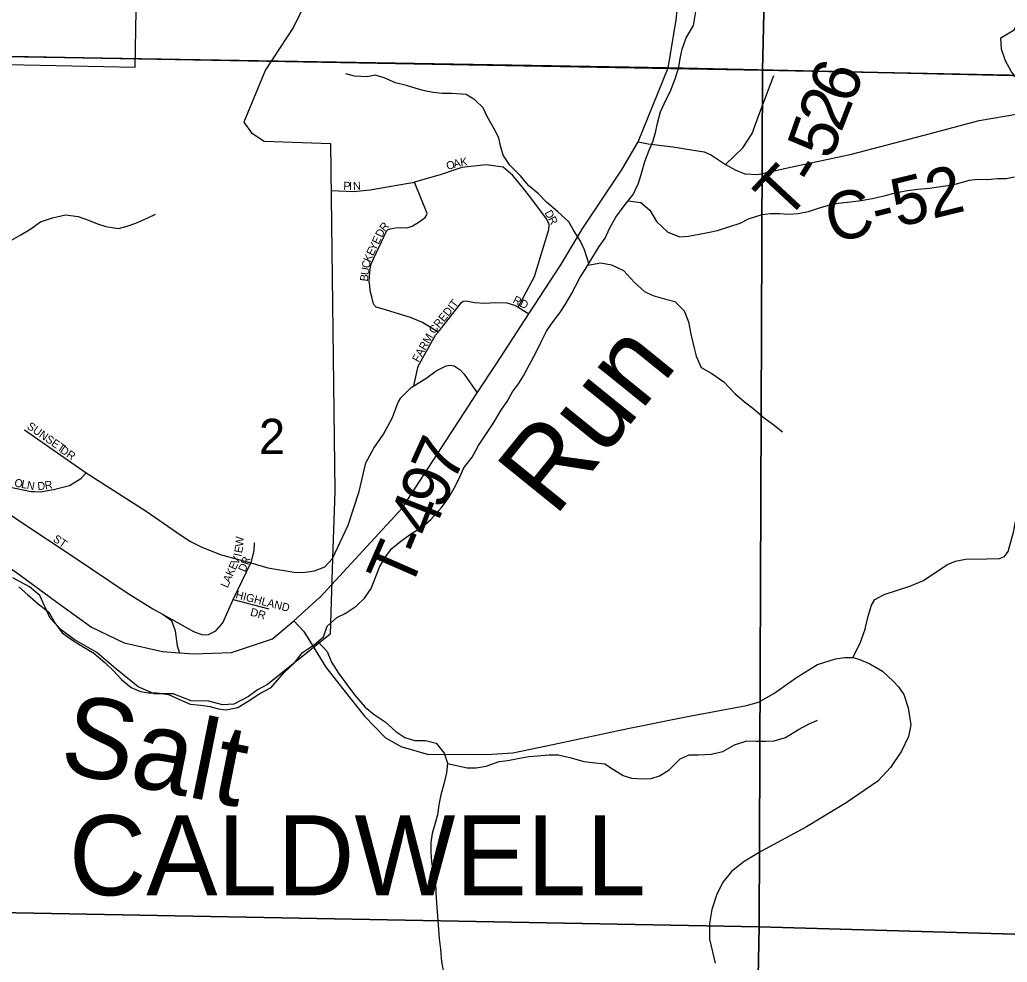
# Model space of a CAD drawing. Extents: x 2043100 to 2470832, y 443715 to 810583.
# Drawn here: x 2248144 to 2254313, y 633122 to 639011 of the extents above; entities that cross this region are included whole.
import ezdxf

# ---------------------------------------------------------------- set-up
doc = ezdxf.new("R2010")
doc.units = 0
for name, color, linetype in [('GM_X_City_Street', 7, 'Continuous'), ('GM_X_City_Street_Text', 7, 'Continuous'), ('GM_X_Corporation', 7, 'Continuous'), ('GM_X_Corporation_Text', 7, 'Continuous'), ('GM_X_County_Road', 7, 'Continuous'), ('GM_X_County_Road_Text', 7, 'Continuous'), ('GM_X_Minor_River', 7, 'Continuous'), ('GM_X_Minor_River_Text', 7, 'Continuous'), ('GM_X_Section', 7, 'Continuous'), ('GM_X_Section_Text', 7, 'Continuous'), ('GM_X_State_Route', 7, 'Continuous'), ('GM_X_Township', 7, 'Continuous'), ('GM_X_Township_Road', 7, 'Continuous'), ('GM_X_Township_Road_Text', 7, 'Continuous'), ('GM_X_Township_Subdivision', 7, 'Continuous'), ('GM_X_Township_Subdivision_Text', 7, 'Continuous')]:
    doc.layers.add(name, color=color, linetype=linetype)

msp = doc.modelspace()

# ---------------------------------------------------------------- linework, layer by layer
at = {"layer": 'GM_X_City_Street'}
for points in [[(2246916.4, 636617.1), (2246919.8, 636615.1), (2247083.8, 636528.3), (2247237.6, 636457.6), (2247393.3, 636382.9), (2247469.1, 636346.6), (2247533, 636314.3), (2247678.5, 636203.6), (2247905.2, 636042.7), (2248145.2, 635877.5), (2248484.3, 635651.9), (2248815.4, 635430.4), (2248975, 635329.7), (2249040.9, 635295.4), (2249092.7, 635257.2), (2249114.4, 635193), (2249128.1, 635098.9), (2249142.1, 635055.9)], [(2248173.5, 636448), (2248559.7, 636180.3), (2248933.5, 635940.5), (2249150.9, 635789.5), (2249210.7, 635751.2), (2249278.6, 635716.9), (2249396.4, 635670.4), (2249518.3, 635635.9), (2249587.9, 635616.6), (2249694.1, 635587.2), (2249858.6, 635559.7), (2249912.7, 635557), (2249986.4, 635566.8), (2250049.8, 635592.4), (2250098.3, 635644.2)], [(2248236.6, 636062.6), (2248237.1, 636062.6), (2248274, 636061.2), (2248356, 636074.9), (2248456.1, 636100.5), (2248526.3, 636144.3), (2248559.7, 636180.3)], [(2247905.2, 636042.7), (2247928, 636068.5), (2247964.1, 636092.4), (2248006.1, 636104.3), (2248076.1, 636092), (2248216, 636063.4), (2248236.6, 636062.6)], [(2249040.9, 635295.4), (2249230.4, 635188.6), (2249286.4, 635168.3), (2249324.4, 635170.2), (2249368.4, 635192), (2249412.6, 635241.9), (2249478, 635387.9), (2249587.9, 635616.6), (2249592.2, 635625.6), (2249608.4, 635695.3), (2249610.7, 635741.7)], [(2249478, 635387.9), (2249701, 635330.9)]]:
    msp.add_lwpolyline(points, dxfattribs=at)
at = {"layer": 'GM_X_Corporation'}
for points in [[(2247477.8, 638744.4), (2248866.3, 638715.3), (2248899.3, 640602.3)], [(2250001.5, 639264.4), (2249855.6, 638965.3), (2249678.9, 638698.2), (2249544.1, 638370.9), (2249592.3, 638303.3), (2249671.3, 638252.1), (2250085.7, 638238.4), (2250112.3, 636062.9), (2250098.3, 635644.2), (2250082.7, 635170.9), (2249693.1, 634856.4), (2249628.9, 634824.7), (2249572.8, 634782.8), (2249482.6, 634735.1), (2249410.6, 634729.4), (2249326.7, 634753.8), (2249214.7, 634756.2), (2249102.8, 634798.7), (2248984.8, 634799.1), (2248885, 634843.6), (2248743.5, 634958.2), (2248625.9, 635056.8), (2248484.2, 635139.4), (2248402.5, 635199.8), (2248334.7, 635272.1), (2248269.3, 635412.5), (2248205.5, 635466.8), (2248101.8, 635523.3)]]:
    msp.add_lwpolyline(points, dxfattribs=at)
at = {"layer": 'GM_X_County_Road'}
msp.add_lwpolyline([(2252008.4, 638247.2), (2252069.4, 638235.8), (2252223.7, 638217), (2252354.1, 638195.9), (2252420.2, 638184.4), (2252466.4, 638164.7), (2252553, 638107.3), (2252613.3, 638073.7), (2252673.5, 638048.1), (2252755.7, 638044.7), (2252939.6, 638086.3), (2253339.4, 638171.6), (2253787, 638287.3), (2254138.7, 638380.2), (2254380.7, 638422.2), (2254753.4, 638513.8), (2255076.6, 638545.9), (2255374.8, 638639.7), (2255458.5, 638669.6), (2255476.2, 638675.4)], dxfattribs=at)
at = {"layer": 'GM_X_Minor_River'}
for points in [[(2252353.3, 638975.5), (2252368.3, 639062.6)], [(2249715.3, 634839.6), (2249793.6, 634931.1), (2249861.5, 634993.5), (2249911.4, 635057.8), (2249985.3, 635108.2), (2250041.3, 635154.5), (2250065, 635222.7), (2250125, 635277), (2250177, 635301.2), (2250247, 635347.6), (2250298.9, 635395.9), (2250340.7, 635458.2), (2250392.3, 635590.6), (2250430.1, 635654.8), (2250467.9, 635707), (2250525.9, 635753.4), (2250585.9, 635795.7), (2250659.8, 635842.1), (2250711.8, 635888.3), (2250779.6, 635962.8), (2250825.4, 636025), (2250857.3, 636083.2), (2250885.1, 636135.4), (2250918.9, 636211.7), (2250970.7, 636278), (2251010.5, 636350.3), (2251064.3, 636432.6), (2251102.1, 636488.8), (2251153.9, 636575.2), (2251189.7, 636625.4), (2251223.6, 636685.6), (2251259.4, 636735.8), (2251291.3, 636786), (2251329.1, 636856.3), (2251368.9, 636930.6), (2251402.7, 636998.8), (2251434.4, 637065), (2251476.3, 637125.3), (2251518.2, 637179.6), (2251554, 637233.8), (2251591.8, 637298), (2251643.5, 637398.4), (2251677.4, 637450.6), (2251719.2, 637518.9), (2251765, 637593.2), (2251800.8, 637645.4), (2251828.6, 637705.6), (2251868.4, 637777.9), (2251920.2, 637848.2), (2251976.1, 637918.5), (2252009.9, 637988.8), (2252025.7, 638042.9), (2252049.4, 638125.1), (2252077.1, 638195.3), (2252100.9, 638253.5), (2252118.7, 638313.7), (2252128.5, 638363.8), (2252146.2, 638435.9), (2252180, 638508.2), (2252207.9, 638560.4), (2252239.6, 638640.6), (2252261.3, 638714.8), (2252271.1, 638768.9), (2252282.9, 638827.1), (2252306.6, 638897.3), (2252353.3, 638975.5)], [(2254425.3, 638052.9), (2254439.4, 638123.5), (2254439.1, 638191.6), (2254434.8, 638259.7), (2254446.5, 638325.8), (2254464.3, 638396), (2254458, 638446), (2254445.8, 638502), (2254419.4, 638560), (2254381, 638633.9), (2254340.7, 638685.8), (2254302.3, 638753.8), (2254277.9, 638827.7), (2254273.6, 638897.8), (2254356.5, 638948.5), (2254384.3, 638999.3)], [(2251699.6, 637486.9), (2251672.8, 637572.8), (2251648.5, 637626.7), (2251604.1, 637696.6), (2251573.8, 637748.5), (2251503.4, 637812.3), (2251434.9, 637870.1), (2251384.6, 637922), (2251324.2, 637973.8), (2251269.8, 638037.6), (2251205.3, 638101.4), (2251165, 638165.3), (2251148.7, 638223.3), (2251136.4, 638273.3), (2251108.1, 638329.3), (2251063.6, 638407.2), (2251039.3, 638461.2), (2250987, 638511), (2250932.7, 638542.8), (2250844.5, 638550.4), (2250784.3, 638550.2), (2250726.1, 638555.9), (2250672, 638565.7), (2250621.8, 638581.5), (2250559.5, 638599.3), (2250491.3, 638617), (2250421, 638648.7), (2250364.7, 638664.5), (2250314.7, 638654.3), (2250236.5, 638657.9), (2250182.2, 638673.7)], [(2251945.3, 637879.8), (2252024.4, 637868.7), (2252080.8, 637820.9), (2252121.2, 637750.9), (2252193.7, 637683.2), (2252268, 637653.4), (2252322.1, 637657.7), (2252388.2, 637670), (2252442.3, 637682.2), (2252502.4, 637694.5), (2252580.5, 637718.9), (2252644.6, 637739.2), (2252696.6, 637767.5), (2252782.7, 637793.9), (2252834.8, 637800.1), (2252892.9, 637800.4), (2252947.1, 637796.6), (2253007.2, 637800.9), (2253071.3, 637813.2), (2253141.4, 637835.5), (2253207.5, 637853.8), (2253257.5, 637864), (2253333.7, 637872.4), (2253399.8, 637880.7), (2253470, 637893), (2253544.1, 637911.3), (2253622.2, 637931.7), (2253690.3, 637944), (2253754.4, 637952.3), (2253828.6, 637958.7), (2253884.7, 637966.9), (2253942.8, 637975.2), (2253996.9, 637985.4), (2254077, 638007.8), (2254129.1, 638014), (2254191.3, 638012.3), (2254253.4, 638018.6), (2254307.5, 638018.8), (2254359.6, 638029)], [(2248078.1, 637625.3), (2248151.6, 637666), (2248207.3, 637700.5), (2248274.8, 637747.1), (2248348.5, 637773.7), (2248430.3, 637792.4), (2248510.4, 637781.1), (2248574.5, 637757.7), (2248630.7, 637736.1), (2248682.8, 637718.6), (2248760.8, 637707.2), (2248814.6, 637721.7), (2248870.4, 637740.2), (2248940.1, 637770.8), (2248991.9, 637795.3)], [(2251693.1, 637476.3), (2251775.4, 637491.1), (2251841.7, 637479.4), (2251916, 637443.6), (2251984.5, 637369.8), (2252046.9, 637312), (2252099.1, 637288.2), (2252171.4, 637266.5), (2252237.7, 637250.8), (2252294.1, 637191), (2252322.4, 637123), (2252336.8, 637046.9), (2252357.2, 636958.9), (2252369.5, 636908.9), (2252401.9, 636839), (2252468.2, 636801.2), (2252542.6, 636747.4), (2252611.1, 636675.7), (2252671.5, 636623.9), (2252723.8, 636584), (2252794.2, 636524.3), (2252848.6, 636484.4), (2252908.9, 636436.6)], [(2248139, 635468.4), (2248193.4, 635418.8), (2248259.9, 635361.4), (2248326.3, 635309.9), (2248362.8, 635242.2), (2248409.3, 635180.5), (2248485.8, 635125.2), (2248544, 635089.6), (2248606.3, 635052.2), (2248676.8, 634994.7), (2248731.2, 634941.2), (2248781.6, 634887.5), (2248840, 634838), (2248898.2, 634814.5), (2248948.2, 634804.9), (2249002.2, 634805.4), (2249074.2, 634794), (2249142.5, 634762.6), (2249208.6, 634735.1), (2249274.7, 634727.7), (2249334.7, 634720.2), (2249384.8, 634704.6), (2249434.8, 634699), (2249506.6, 634713.7), (2249572.2, 634752.3), (2249643.7, 634800.9), (2249715.3, 634839.6)], [(2250005.8, 635125.1), (2250065.7, 635064.5), (2250092.1, 634996.5), (2250136.5, 634928.6), (2250186.9, 634856.7), (2250235.4, 634792.8), (2250301.9, 634715), (2250358.2, 634669.2), (2250426.6, 634623.4), (2250493, 634563.7), (2250549.3, 634525.8), (2250609.5, 634508.1), (2250679.7, 634508.4), (2250746, 634490.7), (2250796.4, 634428.8), (2250816.7, 634366.8), (2250810.9, 634304.7), (2250793.2, 634234.5), (2250775.5, 634168.4), (2250761.7, 634106.2), (2250753.9, 634042.1), (2250740.1, 633990), (2250720.4, 633925.8), (2250712.6, 633869.7), (2250712.9, 633809.6), (2250717.1, 633749.5), (2250729.5, 633671.5), (2250741.8, 633621.5), (2250744, 633555.4), (2250748.3, 633493.3), (2250752.6, 633439.3), (2250765.4, 633271.1), (2250773.7, 633203.1), (2250780, 633125), (2250790.3, 633071)], [(2250816.4, 634363.6), (2250939.1, 634337.3), (2250995.3, 634337.5), (2251057.4, 634347.8), (2251139.5, 634376.2), (2251193.6, 634382.5), (2251255.7, 634394.8), (2251323.8, 634407.1), (2251377.9, 634411.3), (2251450.1, 634417.6), (2251508.2, 634417.9), (2251588.5, 634400.2), (2251668.8, 634376.5), (2251723, 634370.8), (2251799.2, 634361.1), (2251853.5, 634325.3), (2251913.8, 634289.5), (2251966, 634271.7), (2252036.2, 634268), (2252088.3, 634270.2), (2252140.4, 634286.5), (2252200.4, 634324.8), (2252270.2, 634393.2), (2252326.3, 634417.4), (2252382.4, 634417.7), (2252464.6, 634422.1), (2252536.7, 634438.4), (2252608.7, 634480.8), (2252686.8, 634505.1), (2252745, 634503.4), (2252803.1, 634503.6), (2252857.2, 634505.9), (2252927.3, 634526.2), (2253009.3, 634576.6), (2253067.3, 634606.9), (2253127.4, 634635.2)]]:
    msp.add_lwpolyline(points, dxfattribs=at)
at = {"layer": 'GM_X_Section'}
for points in [[(2252910.3, 644018.4), (2252784.6, 638695), (2247507.7, 638791.7), (2247636.8, 644123.4)], [(2252910.3, 644018.4), (2258237.7, 643923), (2258136.1, 638587.9), (2252784.6, 638695)], [(2247507.7, 638791.7), (2252784.6, 638695), (2252763.7, 633342.5), (2247455.2, 633443.4)], [(2258136.1, 638587.9), (2258053.6, 633190.7), (2252763.7, 633342.5), (2252784.6, 638695)], [(2252763.7, 633342.5), (2252657.4, 628097.1), (2247392.1, 628154.7), (2247455.2, 633443.4)], [(2258053.6, 633190.7), (2258045.4, 632868.5), (2257942.2, 628047.3), (2252657.4, 628097.1), (2252763.7, 633342.5)]]:
    msp.add_lwpolyline(points, close=True, dxfattribs=at)
at = {"layer": 'GM_X_State_Route'}
for points in [[(2250017.6, 635400.9), (2250018.5, 635401.7), (2250533.3, 635960.1), (2251002.7, 636678.7), (2251124.7, 636865.5), (2251324.4, 637172.5), (2251524.5, 637479.9), (2251662.9, 637707.5), (2251908.4, 638076.2), (2252008.4, 638247.2), (2252195.8, 638709.3), (2252245.3, 639008.3), (2252267.6, 639228.6)], [(2246834.2, 636179.1), (2247009.2, 636135.6), (2247247.5, 636073.3), (2247254.5, 636071.5), (2247504.5, 635951.5), (2247825.6, 635751.8), (2248116.4, 635563.4), (2248367, 635378.3), (2248593.1, 635214.6), (2248797.7, 635116.7), (2249035.5, 635063.5), (2249142.1, 635055.9), (2249230.3, 635049.5), (2249466.8, 635056.5), (2249723.7, 635142), (2249857.4, 635256.1)], [(2249857.4, 635256.1), (2250014.6, 635398.1), (2250017.6, 635400.9)], [(2249857.4, 635256.1), (2249918, 635190.5), (2249929.2, 635172.1), (2249955.6, 635129)], [(2249955.6, 635129), (2250055.8, 634965), (2250161, 634831.6), (2250298.4, 634660.3), (2250427.6, 634527), (2250524.1, 634469.6), (2250698.7, 634420.9), (2250937, 634422.7), (2251063.1, 634419.7), (2251225.2, 634431), (2251475.1, 634483.1), (2251942.9, 634582.9), (2252304.8, 634655.9), (2252684.7, 634727), (2252758.7, 634747.6), (2252854.4, 634800.5), (2252997.3, 634900.4), (2253001.7, 634903.4)], [(2253001.7, 634903.4), (2253019.7, 634916), (2253127.3, 634983), (2253241.2, 635017.9), (2253299.7, 635026.9), (2253349.2, 635026.8), (2253385.2, 635014.7), (2253455.7, 634985.6), (2253534.1, 634940.1), (2253600.6, 634878.5), (2253635, 634842.6), (2253667.4, 634794.8), (2253694, 634710.8), (2253710.8, 634604.7), (2253697.4, 634532.5), (2253652, 634439.9), (2253584.7, 634339.2), (2253505.3, 634252.4), (2253306.1, 634118.5), (2253058.9, 633968.3), (2252773.7, 633813.7), (2252670.1, 633750.8), (2252590.5, 633688), (2252538.9, 633623.5), (2252499.4, 633547), (2252468.1, 633452.5), (2252452.8, 633364.2), (2252453.5, 633266), (2252488.7, 633116)]]:
    msp.add_lwpolyline(points, dxfattribs=at)
at = {"layer": 'GM_X_Township'}
for points in [[(2255374.8, 638639.7), (2252195.8, 638709.3), (2247807.2, 638785), (2247504, 638792.8), (2247545.4, 640176.7), (2247643.8, 645707.3), (2247707.5, 648351.7), (2247823.1, 655129.8), (2247861, 657353.3), (2247894.8, 659332.6), (2247905.3, 659948.7), (2248027.9, 667139.4), (2248085.7, 670382.7), (2248089.5, 670694.5), (2250661.2, 670642.8), (2256458.7, 670526.3)], [(2234072.5, 630720.1), (2234171.5, 633589.1), (2234162.8, 635122.7), (2234148.8, 638924.2), (2234148.5, 638991.7), (2234206.5, 638990.6), (2234430.6, 638986.4), (2235869.8, 638968.1), (2240076, 638887.1), (2240382.5, 638881.1), (2242084.2, 638871.4), (2242283.4, 638880.3), (2243266.9, 638868.3), (2243764.8, 638853.6), (2244077.4, 638844.4), (2244403.6, 638834.8), (2244966.2, 638818.3), (2245281.8, 638809), (2247504, 638792.8), (2247807.2, 638785), (2252195.8, 638709.3), (2255374.8, 638639.7)]]:
    msp.add_lwpolyline(points, dxfattribs=at)
at = {"layer": 'GM_X_Township_Road'}
for points in [[(2252553, 638107.3), (2252660.6, 638211.4), (2252719.5, 638300.4), (2252762.1, 638415.3), (2252855, 638663.1)], [(2250737.6, 636809.9), (2250751, 636819.9), (2250808.9, 636848.8), (2250832.3, 636852.2), (2250857.9, 636848.8), (2250895.8, 636823.2), (2250920.3, 636795.4), (2251002.7, 636678.7)], [(2250509.6, 636623.7), (2250526, 636648.3), (2250552.8, 636675), (2250590.6, 636712.9), (2250606.4, 636722.6), (2250682, 636768.6), (2250737.6, 636809.9)], [(2250098.3, 635644.2), (2250196.4, 635852.7), (2250265.4, 636062.2), (2250305.5, 636242.7), (2250356.7, 636334.1), (2250416.9, 636421), (2250472.6, 636525.7), (2250508.2, 636621.5), (2250509.6, 636623.7)], [(2253427.9, 635213.3), (2253428.1, 635213.8), (2253444.3, 635284.5), (2253465.5, 635353), (2253487, 635387.4), (2253544.7, 635420.2), (2253704.3, 635472.5), (2253789.9, 635507.8), (2253873.3, 635563), (2253940.9, 635608.1), (2253990.7, 635628.8), (2254052.6, 635639.6), (2254186.8, 635641.5), (2254264.9, 635644.5), (2254296.8, 635657), (2254318.4, 635687.4), (2254352.9, 635808.1), (2254364, 635874.5), (2254385.1, 635946.9), (2254464.3, 636014.2), (2254573.7, 636071.8), (2254603.6, 636080.6), (2254606.1, 636081.3)], [(2253349.2, 635026.8), (2253394.5, 635115.4), (2253425.4, 635202.1), (2253427.9, 635213.3)]]:
    msp.add_lwpolyline(points, dxfattribs=at)
at = {"layer": 'GM_X_Township_Subdivision'}
for points in [[(2251283.6, 637966), (2251225.5, 638036.6), (2251165.3, 638090.1), (2251058.4, 638103.5), (2250907, 638087.9), (2250777.8, 638043.3), (2250610.4, 637995.1), (2250599.6, 637992), (2250561.1, 637985.2)], [(2250408, 637204.2), (2250370, 637215.9), (2250361.4, 637226.1), (2250352.4, 637241.6), (2250343.3, 637280.3), (2250334.3, 637316.5), (2250330.5, 637353.3), (2250327.8, 637373.3), (2250329.1, 637408.2), (2250334.3, 637453.4), (2250339.8, 637485), (2250435.7, 637690.7), (2250446.3, 637700.1), (2250458.7, 637705), (2250491, 637711.4), (2250523.9, 637712.1), (2250564.1, 637710.9), (2250578, 637714.3), (2250594.9, 637721.7), (2250638.8, 637747.5), (2250676.3, 637776), (2250683.9, 637786.6), (2250689.5, 637800.2), (2250610.4, 637995.1)], [(2250561.1, 637985.2), (2250334.5, 637945.2), (2250229.8, 637935.2), (2250089.3, 637940.8)], [(2251257.8, 637213.9), (2251359.1, 637405.9), (2251450.5, 637700.1), (2251451.6, 637731.3), (2251436, 637765.9), (2251331.9, 637907.1), (2251283.6, 637966)], [(2250606.4, 636722.6), (2250632.9, 636845.5), (2250742.1, 637039.4), (2250757.8, 637059.2), (2250903.6, 637243.3), (2250914.7, 637253.3), (2250932.6, 637254.4), (2250984.9, 637244.4), (2251049.5, 637239.9), (2251116.3, 637244.4), (2251187.6, 637242.2), (2251235.5, 637227.7), (2251239.3, 637225.3)], [(2250757.8, 637059.2), (2250659.7, 637118.4), (2250585.1, 637150.1), (2250408, 637204.2)], [(2251239.3, 637225.3), (2251257.8, 637213.9), (2251324.4, 637172.5)]]:
    msp.add_lwpolyline(points, dxfattribs=at)

# ---------------------------------------------------------------- texts
at = {"layer": 'GM_X_City_Street_Text'}
for s, rotation, p in [('SUNSET', 325.09473, (2248184.8, 636460.3)), ('DR', 325.49206, (2248391.6, 636310.7)), ('O', 349.27295, (2248107.8, 636095.4)), ('L', 349.28041, (2248151, 636087.2)), ('N', 349.27295, (2248185.6, 636080.7)), ('D', 5.62951, (2248257.5, 636070.8)), ('R', 9.19644, (2248304.7, 636075.6)), ('ST', 325.29786, (2248347.6, 635756.3)), ('W', 86.57076, (2249540.4, 635717.5)), ('E', 78.3097, (2249532.2, 635675.2)), ('V', 66.07523, (2249506.5, 635601.8)), ('I', 78.99475, (2249528, 635653.8)), ('R', 71.28583, (2249571.8, 635600.9)), ('K', 66.08665, (2249474.4, 635529.4)), ('E', 66.08744, (2249492.3, 635569.6)), ('D', 66.2505, (2249552.4, 635556.2)), ('A', 66.07523, (2249456.6, 635489.2)), ('L', 66.08744, (2249442.3, 635457)), ('HIGHLAND', 345.57873, (2249488.8, 635396.8)), ('DR', 344.47401, (2249580.7, 635289))]:
    msp.add_text(s, height=50, rotation=rotation, dxfattribs=at).set_placement(p)
at = {"layer": 'GM_X_Corporation_Text'}
msp.add_text('CALDWELL', height=500, rotation=0.00001, dxfattribs=at).set_placement((2248451.6, 633540.4))
at = {"layer": 'GM_X_County_Road_Text'}
msp.add_text('C-52', height=300, rotation=13.78, dxfattribs=at).set_placement((2253218.2, 637612.3))
at = {"layer": 'GM_X_Minor_River_Text'}
for s, height, rotation, p in [('Run', 499.95, 51.0019, (2251486.9, 635898.4)), ('Salt', 499.98, 348.64321, (2248380, 634318.6))]:
    msp.add_text(s, height=height, rotation=rotation, dxfattribs=at).set_placement(p)
at = {"layer": 'GM_X_Section_Text'}
msp.add_text('2', height=220.8, rotation=0.00001, dxfattribs=at).set_placement((2249638.4, 636296.6))
at = {"layer": 'GM_X_Township_Road_Text'}
for s, rotation, p in [('6', 68.56869, (2253342.1, 638472.5)), ('2', 68.72523, (2253275.1, 638300.5)), ('5', 70.55617, (2253214.5, 638128.7)), ('T', 47.1036, (2252928, 637745.8)), ('-', 58.20016, (2253119.1, 637960.5)), ('7', 65.69774, (2250852.1, 636108.6)), ('9', 68.71365, (2250786.6, 635940.3)), ('4', 68.72102, (2250719.6, 635768.1)), ('T', 66.40129, (2250578.3, 635436.1)), ('-', 67.8801, (2250671.4, 635649.5))]:
    msp.add_text(s, height=300, rotation=rotation, dxfattribs=at).set_placement(p)
at = {"layer": 'GM_X_Township_Subdivision_Text'}
for s, rotation, p in [('O', 15.87633, (2250817.1, 638071.8)), ('A', 15.8709, (2250859.4, 638083.9)), ('K', 8.84421, (2250900.1, 638095.6)), ('P', 357.23991, (2250165, 637949)), ('I', 357.21899, (2250200.2, 637947.3)), ('N', 3.37914, (2250227.9, 637946.3)), ('D', 300.00786, (2251421.2, 637804.2)), ('R', 49.83065, (2250424.4, 637683.7)), ('R', 297.27104, (2251442.9, 637766.6)), ('D', 64.33654, (2250407.2, 637646.9)), ('Y', 64.34401, (2250367.1, 637563.6)), ('E', 64.33928, (2250386.2, 637603.2)), ('E', 64.33928, (2250351.9, 637531.9)), ('C', 80.53368, (2250329.5, 637455.8)), ('K', 67.22041, (2250335.1, 637491.9)), ('U', 82.23778, (2250323.6, 637412.6)), ('B', 82.25451, (2250318.2, 637373.3)), ('CREDIT', 51.34285, (2250733.8, 637043.8)), ('RD', 333.43981, (2251219.7, 637244.1)), ('FARM', 60.8015, (2250636.1, 636866.6))]:
    msp.add_text(s, height=50, rotation=rotation, dxfattribs=at).set_placement(p)

doc.saveas('drawing.dxf')
